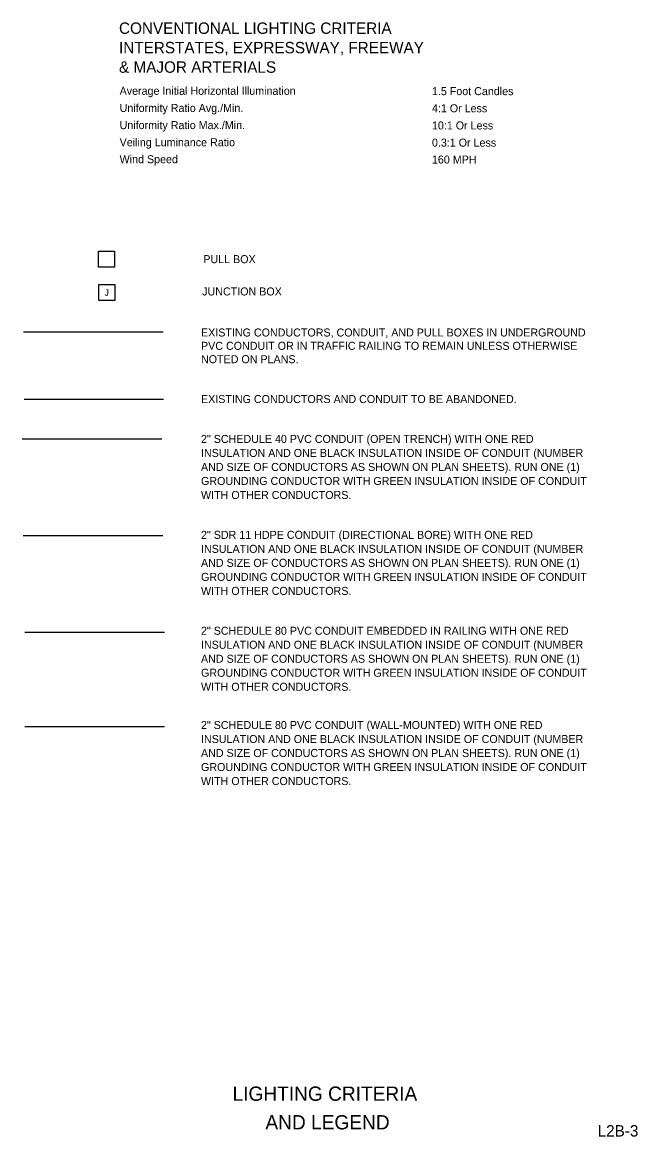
# Model space of a CAD drawing. Extents: x -0.6 to 15.1, y -0.9 to 9.2.
# Drawn here: x 9.77 to 15.15, y -0.65 to 9.1 of the extents above; entities that cross this region are included whole.
import ezdxf

# ---------------------------------------------------------------- set-up
doc = ezdxf.new("R2010")
doc.units = 0
for name, color, linetype in [('Conduit', 7, 'Continuous'), ('JunctBoxA', 7, 'Continuous'), ('LiteCond_ep', 7, 'Continuous'), ('Miscellaneous1', 7, 'Continuous'), ('Miscellaneous3', 7, 'Continuous'), ('Miscellaneous7', 7, 'Continuous'), ('Miscellaneous8', 7, 'Continuous'), ('PullBox', 7, 'Continuous'), ('TextLabel', 7, 'Continuous'), ('TextMisc', 7, 'Continuous'), ('TextNotes', 7, 'Continuous'), ('TextShtNo', 7, 'Continuous')]:
    doc.layers.add(name, color=color, linetype=linetype)

msp = doc.modelspace()

# ---------------------------------------------------------------- linework, layer by layer
at = {"layer": 'Conduit'}
msp.add_line((9.7769, 6.3923), (10.9973, 6.3923), dxfattribs=at)
at = {"layer": 'LiteCond_ep'}
msp.add_line((9.7804, 5.8048), (11.002, 5.8048), dxfattribs=at)
at = {"layer": 'Miscellaneous1'}
msp.add_line((9.7653, 5.4561), (10.9858, 5.4561), dxfattribs=at)
at = {"layer": 'Miscellaneous3'}
msp.add_line((9.7731, 4.6104), (10.9936, 4.6104), dxfattribs=at)
at = {"layer": 'Miscellaneous7'}
msp.add_line((9.7879, 3.7655), (11.0083, 3.7655), dxfattribs=at)
at = {"layer": 'Miscellaneous8'}
msp.add_line((9.7879, 2.941), (11.0083, 2.941), dxfattribs=at)
at = {"layer": 'PullBox'}
for p, q in [((10.4328, 6.9568), (10.4328, 7.0975)), ((10.4328, 7.0975), (10.5734, 7.0975)), ((10.5734, 7.0975), (10.5734, 6.9568)), ((10.5734, 6.9568), (10.4328, 6.9568)), ((10.4336, 6.8061), (10.5742, 6.8061)), ((10.4336, 6.6654), (10.4336, 6.8061)), ((10.5742, 6.8061), (10.5742, 6.6654)), ((10.5742, 6.6654), (10.4336, 6.6654))]:
    msp.add_line(p, q, dxfattribs=at)

# ---------------------------------------------------------------- texts
at = {"layer": 'JunctBoxA'}
msp.add_text('J', height=0.0563, dxfattribs=at).set_placement((10.4848, 6.7076))
at = {"layer": 'TextLabel'}
for s, p in [('CONVENTIONAL LIGHTING CRITERIA', (10.6114, 8.9983)), ('INTERSTATES, EXPRESSWAY, FREEWAY', (10.6114, 8.8283)), ('& MAJOR ARTERIALS', (10.6114, 8.6583))]:
    msp.add_text(s, height=0.1, dxfattribs=at).set_placement(p)
at = {"layer": 'TextMisc'}
for s, p in [('PULL BOX', (11.3491, 6.9932)), ('JUNCTION BOX', (11.3389, 6.7108)), ('EXISTING CONDUCTORS, CONDUIT, AND PULL BOXES IN UNDERGROUND ', (11.3287, 6.3519)), ('PVC CONDUIT OR IN TRAFFIC RAILING TO REMAIN UNLESS OTHERWISE ', (11.3287, 6.2353)), ('NOTED ON PLANS.', (11.3287, 6.1186)), ('EXISTING CONDUCTORS AND CONDUIT TO BE ABANDONED.', (11.3287, 5.7698)), ('2" SCHEDULE 40 PVC CONDUIT (OPEN TRENCH) WITH ONE RED ', (11.3287, 5.4211)), ('INSULATION AND ONE BLACK INSULATION INSIDE OF CONDUIT (NUMBER ', (11.3287, 5.2986)), ('AND SIZE OF CONDUCTORS AS SHOWN ON PLAN SHEETS). RUN ONE (1) ', (11.3287, 5.1761)), ('GROUNDING CONDUCTOR WITH GREEN INSULATION INSIDE OF CONDUIT ', (11.3287, 5.0536)), ('WITH OTHER CONDUCTORS.', (11.3287, 4.9311)), ('2" SDR 11 HDPE CONDUIT (DIRECTIONAL BORE) WITH ONE RED ', (11.3287, 4.5823)), ('INSULATION AND ONE BLACK INSULATION INSIDE OF CONDUIT (NUMBER ', (11.3287, 4.4598)), ('AND SIZE OF CONDUCTORS AS SHOWN ON PLAN SHEETS). RUN ONE (1) ', (11.3287, 4.3373)), ('GROUNDING CONDUCTOR WITH GREEN INSULATION INSIDE OF CONDUIT ', (11.3287, 4.2148)), ('WITH OTHER CONDUCTORS.', (11.3287, 4.0923)), ('2" SCHEDULE 80 PVC CONDUIT EMBEDDED IN RAILING WITH ONE RED ', (11.3287, 3.7436)), ('INSULATION AND ONE BLACK INSULATION INSIDE OF CONDUIT (NUMBER ', (11.3287, 3.6211)), ('AND SIZE OF CONDUCTORS AS SHOWN ON PLAN SHEETS). RUN ONE (1) ', (11.3287, 3.4986)), ('GROUNDING CONDUCTOR WITH GREEN INSULATION INSIDE OF CONDUIT ', (11.3287, 3.3761)), ('WITH OTHER CONDUCTORS.', (11.3287, 3.2536)), ('2" SCHEDULE 80 PVC CONDUIT (WALL-MOUNTED) WITH ONE RED ', (11.3287, 2.9191)), ('INSULATION AND ONE BLACK INSULATION INSIDE OF CONDUIT (NUMBER ', (11.3287, 2.7966)), ('AND SIZE OF CONDUCTORS AS SHOWN ON PLAN SHEETS). RUN ONE (1) ', (11.3287, 2.6741)), ('GROUNDING CONDUCTOR WITH GREEN INSULATION INSIDE OF CONDUIT ', (11.3287, 2.5516)), ('WITH OTHER CONDUCTORS.', (11.3287, 2.4291))]:
    msp.add_text(s, height=0.07, rotation=360, dxfattribs=at).set_placement(p)
for s, p in [('   LIGHTING CRITERIA    ', (11.4651, -0.3324)), ('       AND LEGEND       ', (11.5669, -0.5824))]:
    msp.add_text(s, height=0.125, dxfattribs=at).set_placement(p)
at = {"layer": 'TextNotes'}
for s, p in [('Average Initial Horizontal Illumination', (10.6168, 8.4655)), ('1.5 Foot Candles', (13.3491, 8.4626)), ('Uniformity Ratio Avg./Min.', (10.6168, 8.3155)), ('4:1 Or Less', (13.3491, 8.3126)), ('Uniformity Ratio Max./Min.', (10.6168, 8.1655)), ('10:1 Or Less', (13.3491, 8.1626)), ('Veiling Luminance Ratio', (10.6168, 8.0155)), ('0.3:1 Or Less', (13.3491, 8.0126)), ('Wind Speed', (10.6168, 7.8673)), ('160 MPH', (13.3491, 7.8645))]:
    msp.add_text(s, height=0.07, dxfattribs=at).set_placement(p)
at = {"layer": 'TextShtNo'}
msp.add_text('L2B-3 ', height=0.1, dxfattribs=at).set_placement((14.7981, -0.6449))

doc.saveas('drawing.dxf')
